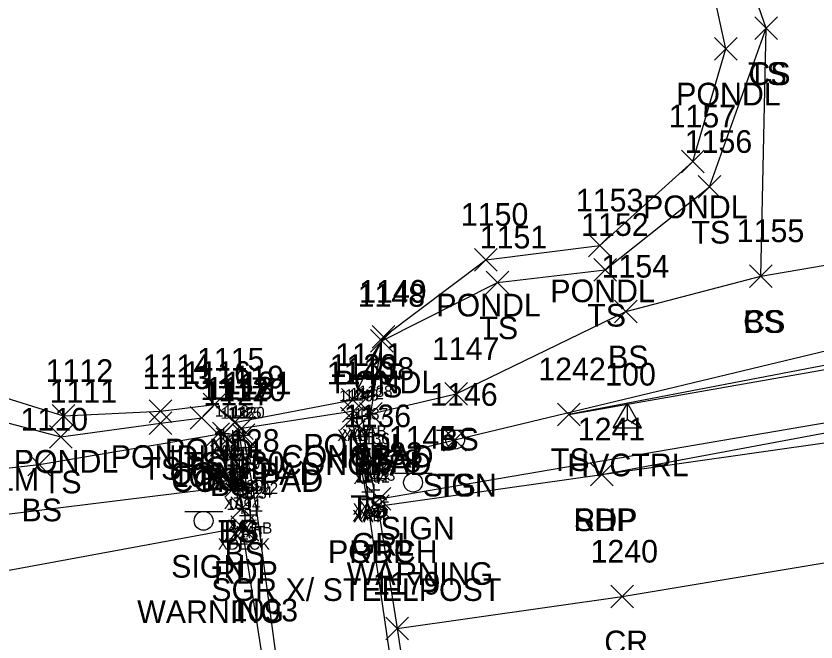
# Model space of a CAD drawing. Extents: x 1497084 to 1499861, y 734741 to 735567.
# Drawn here: x 1498306.3 to 1498376.8, y 735306.9 to 735362.1 of the extents above; entities that cross this region are included whole.
import ezdxf

# ---------------------------------------------------------------- set-up
doc = ezdxf.new("R2010")
doc.units = 0
for name, color, linetype in [('B_A', 7, 'Continuous'), ('B_I', 7, 'Continuous'), ('B_TIC', 7, 'Continuous'), ('BSUBM', 7, 'Continuous'), ('C_A', 7, 'Continuous'), ('C_I', 7, 'Continuous'), ('CPSM', 7, 'Continuous'), ('L_A', 7, 'Continuous'), ('L_C', 7, 'Continuous'), ('L_I', 7, 'Continuous'), ('L_TIC', 7, 'Continuous'), ('LAWE', 7, 'Continuous'), ('LELB', 7, 'Continuous'), ('LS', 7, 'Continuous'), ('P_A', 7, 'Continuous'), ('P_I', 7, 'Continuous'), ('P_TIC', 7, 'Continuous'), ('PET', 7, 'Continuous'), ('PRC', 7, 'Continuous'), ('PSP', 7, 'Continuous'), ('R_A', 7, 'Continuous'), ('R_C', 7, 'Continuous'), ('R_I', 7, 'Continuous'), ('R_TIC', 7, 'Continuous'), ('RGR', 7, 'Continuous'), ('S_A', 7, 'Continuous'), ('S_C', 7, 'Continuous'), ('S_I', 7, 'Continuous'), ('SSGN', 7, 'Continuous')]:
    doc.layers.add(name, color=color, linetype=linetype)

msp = doc.modelspace()

# ---------------------------------------------------------------- linework, layer by layer
at = {"layer": 'B_TIC'}
for p, q in [((1498337.564, 735327.025), (1498337.639, 735327.025)), ((1498335.891, 735326.633), (1498335.966, 735326.633)), ((1498336.333, 735326.701), (1498336.408, 735326.701)), ((1498336.333, 735326.701), (1498336.408, 735326.701)), ((1498336.796, 735326.829), (1498336.872, 735326.829)), ((1498324.607, 735325.287), (1498324.683, 735325.287)), ((1498325.413, 735325.098), (1498325.488, 735325.098)), ((1498326.022, 735325.12), (1498326.097, 735325.12)), ((1498326.343, 735325.152), (1498326.418, 735325.152)), ((1498337.167, 735325.038), (1498337.243, 735325.038)), ((1498337.167, 735325.038), (1498337.243, 735325.038)), ((1498337.347, 735322.858), (1498337.423, 735322.858)), ((1498325.918, 735320.65), (1498325.994, 735320.65)), ((1498337.26, 735320.143), (1498337.335, 735320.143)), ((1498337.872, 735320.321), (1498337.948, 735320.321)), ((1498337.204, 735319.55), (1498337.28, 735319.55)), ((1498337.31, 735319.467), (1498337.386, 735319.467)), ((1498337.31, 735319.467), (1498337.386, 735319.467)), ((1498337.817, 735319.634), (1498337.893, 735319.634)), ((1498326.218, 735318.714), (1498326.294, 735318.714)), ((1498326.218, 735318.714), (1498326.294, 735318.714)), ((1498326.481, 735318.057), (1498326.556, 735318.057)), ((1498326.481, 735318.057), (1498326.556, 735318.057)), ((1498326.967, 735318.137), (1498327.042, 735318.137)), ((1498327.485, 735318.469), (1498327.561, 735318.469)), ((1498326.238, 735317.05), (1498326.314, 735317.05))]:
    msp.add_line(p, q, dxfattribs=at)
for points in [[(1498335.887, 735326.133), (1498335.887, 735327.133)], [(1498336.329, 735326.201), (1498336.329, 735327.201)], [(1498336.329, 735326.201), (1498336.329, 735327.201)], [(1498336.793, 735326.329), (1498336.793, 735327.329)], [(1498337.06, 735327.025), (1498338.06, 735327.025)], [(1498337.56, 735326.525), (1498337.56, 735327.525)], [(1498335.387, 735326.633), (1498336.387, 735326.633)], [(1498335.829, 735326.701), (1498336.829, 735326.701)], [(1498335.829, 735326.701), (1498336.829, 735326.701)], [(1498336.293, 735326.829), (1498337.293, 735326.829)], [(1498324.604, 735324.787), (1498324.604, 735325.787)], [(1498325.409, 735324.598), (1498325.409, 735325.598)], [(1498326.018, 735324.62), (1498326.018, 735325.62)], [(1498326.339, 735324.652), (1498326.339, 735325.652)], [(1498324.104, 735325.287), (1498325.104, 735325.287)], [(1498324.909, 735325.098), (1498325.909, 735325.098)], [(1498325.518, 735325.12), (1498326.518, 735325.12)], [(1498325.839, 735325.152), (1498326.839, 735325.152)], [(1498336.664, 735325.038), (1498337.664, 735325.038)], [(1498336.664, 735325.038), (1498337.664, 735325.038)], [(1498337.164, 735324.538), (1498337.164, 735325.538)], [(1498337.164, 735324.538), (1498337.164, 735325.538)], [(1498336.844, 735322.858), (1498337.844, 735322.858)], [(1498337.344, 735322.358), (1498337.344, 735323.358)], [(1498325.415, 735320.65), (1498326.415, 735320.65)], [(1498325.915, 735320.15), (1498325.915, 735321.15)], [(1498337.256, 735319.643), (1498337.256, 735320.643)], [(1498337.869, 735319.821), (1498337.869, 735320.821)], [(1498336.756, 735320.143), (1498337.756, 735320.143)], [(1498337.201, 735319.05), (1498337.201, 735320.05)], [(1498337.307, 735318.967), (1498337.307, 735319.967)], [(1498337.307, 735318.967), (1498337.307, 735319.967)], [(1498337.369, 735320.321), (1498338.369, 735320.321)], [(1498337.814, 735319.134), (1498337.814, 735320.134)], [(1498336.701, 735319.55), (1498337.701, 735319.55)], [(1498336.807, 735319.467), (1498337.807, 735319.467)], [(1498336.807, 735319.467), (1498337.807, 735319.467)], [(1498337.314, 735319.634), (1498338.314, 735319.634)], [(1498325.715, 735318.714), (1498326.715, 735318.714)], [(1498325.715, 735318.714), (1498326.715, 735318.714)], [(1498326.215, 735318.214), (1498326.215, 735319.214)], [(1498326.215, 735318.214), (1498326.215, 735319.214)], [(1498326.477, 735317.557), (1498326.477, 735318.557)], [(1498326.477, 735317.557), (1498326.477, 735318.557)], [(1498326.963, 735317.637), (1498326.963, 735318.637)], [(1498327.482, 735317.969), (1498327.482, 735318.969)], [(1498325.977, 735318.057), (1498326.977, 735318.057)], [(1498325.977, 735318.057), (1498326.977, 735318.057)], [(1498326.463, 735318.137), (1498327.463, 735318.137)], [(1498326.982, 735318.469), (1498327.982, 735318.469)], [(1498326.235, 735316.55), (1498326.235, 735317.55)], [(1498325.735, 735317.05), (1498326.735, 735317.05)]]:
    msp.add_lwpolyline(points, dxfattribs=at)
at = {"layer": 'BSUBM'}
for points in [[(1498337.164, 735325.038), (1498337.56, 735327.025), (1498335.887, 735326.633), (1498337.201, 735319.55), (1498340.697, 735295.582)], [(1498337.307, 735319.467), (1498337.814, 735319.634), (1498337.869, 735320.321), (1498337.344, 735322.858), (1498337.164, 735325.038), (1498336.793, 735326.829), (1498336.329, 735326.701)], [(1498337.307, 735319.467), (1498337.256, 735320.143), (1498336.329, 735326.701)], [(1498324.604, 735325.287), (1498326.339, 735325.152), (1498327.482, 735318.469)], [(1498326.477, 735318.057), (1498326.963, 735318.137), (1498326.018, 735325.12), (1498325.409, 735325.098), (1498325.915, 735320.65), (1498326.215, 735318.714)], [(1498326.477, 735318.057), (1498326.215, 735318.714)], [(1498327.482, 735318.469), (1498330.708, 735294.208)]]:
    msp.add_lwpolyline(points, dxfattribs=at)
at = {"layer": 'CPSM'}
for p, q in [((1498358.924, 735325.805), (1498360.174, 735327.97)), ((1498361.424, 735325.805), (1498360.174, 735327.97)), ((1498360.174, 735326.527), (1498360.174, 735327.97)), ((1498358.924, 735325.805), (1498360.174, 735326.527)), ((1498360.174, 735326.527), (1498360.174, 735326.527)), ((1498360.174, 735326.527), (1498361.424, 735325.805)), ((1498358.924, 735325.805), (1498361.424, 735325.805))]:
    msp.add_line(p, q, dxfattribs=at)
at = {"layer": 'L_TIC'}
for points in [[(1498371.392, 735360.039), (1498373.392, 735362.039)], [(1498373.392, 735360.039), (1498371.392, 735362.039)], [(1498371.392, 735360.039), (1498373.392, 735362.039)], [(1498373.392, 735360.039), (1498371.392, 735362.039)], [(1498367.843, 735358.236), (1498369.843, 735360.236)], [(1498369.843, 735358.236), (1498367.843, 735360.236)], [(1498364.927, 735348.292), (1498366.927, 735350.292)], [(1498366.927, 735348.292), (1498364.927, 735350.292)], [(1498366.401, 735346.051), (1498368.401, 735348.051)], [(1498368.401, 735346.051), (1498366.401, 735348.051)], [(1498356.753, 735340.882), (1498358.753, 735342.882)], [(1498358.753, 735340.882), (1498356.753, 735342.882)], [(1498346.706, 735339.625), (1498348.706, 735341.625)], [(1498348.706, 735339.625), (1498346.706, 735341.625)], [(1498357.223, 735338.727), (1498359.223, 735340.727)], [(1498359.223, 735338.727), (1498357.223, 735340.727)], [(1498370.933, 735338.178), (1498372.933, 735340.178)], [(1498372.933, 735338.178), (1498370.933, 735340.178)], [(1498370.933, 735338.178), (1498372.933, 735340.178)], [(1498372.933, 735338.178), (1498370.933, 735340.178)], [(1498347.715, 735337.62), (1498349.715, 735339.62)], [(1498349.715, 735337.62), (1498347.715, 735339.62)], [(1498359.02, 735335.053), (1498361.02, 735337.053)], [(1498361.02, 735335.053), (1498359.02, 735337.053)], [(1498337.668, 735332.839), (1498339.668, 735334.839)], [(1498339.668, 735332.839), (1498337.668, 735334.839)], [(1498337.521, 735332.482), (1498339.521, 735334.482)], [(1498339.521, 735332.482), (1498337.521, 735334.482)], [(1498334.984, 735327.258), (1498336.984, 735329.258)], [(1498336.984, 735327.258), (1498334.984, 735329.258)], [(1498344.071, 735327.797), (1498346.071, 735329.797)], [(1498346.071, 735327.797), (1498344.071, 735329.797)], [(1498322.797, 735326.852), (1498324.797, 735328.852)], [(1498324.797, 735326.852), (1498322.797, 735328.852)], [(1498309.467, 735325.847), (1498311.467, 735327.847)], [(1498311.467, 735325.847), (1498309.467, 735327.847)], [(1498318.022, 735326.269), (1498320.022, 735328.269)], [(1498320.022, 735326.269), (1498318.022, 735328.269)], [(1498335.07, 735326.298), (1498337.07, 735328.298)], [(1498337.07, 735326.298), (1498335.07, 735328.298)], [(1498336.56, 735326.025), (1498338.56, 735328.025)], [(1498338.56, 735326.025), (1498336.56, 735328.025)], [(1498336.56, 735326.025), (1498338.56, 735328.025)], [(1498338.56, 735326.025), (1498336.56, 735328.025)], [(1498354.01, 735325.99), (1498356.01, 735327.99)], [(1498356.01, 735325.99), (1498354.01, 735327.99)], [(1498318.026, 735325.223), (1498320.026, 735327.223)], [(1498320.026, 735325.223), (1498318.026, 735327.223)], [(1498321.655, 735325.674), (1498323.655, 735327.674)], [(1498323.655, 735325.674), (1498321.655, 735327.674)], [(1498324.537, 735325.278), (1498326.537, 735327.278)], [(1498326.537, 735325.278), (1498324.537, 735327.278)], [(1498334.887, 735325.633), (1498336.887, 735327.633)], [(1498336.887, 735325.633), (1498334.887, 735327.633)], [(1498323.604, 735324.287), (1498325.604, 735326.287)], [(1498325.604, 735324.287), (1498323.604, 735326.287)], [(1498325.18, 735324.763), (1498327.18, 735326.763)], [(1498327.18, 735324.763), (1498325.18, 735326.763)], [(1498309.248, 735324.019), (1498311.248, 735326.019)], [(1498311.248, 735324.019), (1498309.248, 735326.019)], [(1498323.107, 735324.253), (1498325.107, 735326.253)], [(1498325.107, 735324.253), (1498323.107, 735326.253)], [(1498323.107, 735324.253), (1498325.107, 735326.253)], [(1498325.107, 735324.253), (1498323.107, 735326.253)], [(1498323.937, 735323.789), (1498325.937, 735325.789)], [(1498325.937, 735323.789), (1498323.937, 735325.789)], [(1498325.339, 735324.152), (1498327.339, 735326.152)], [(1498327.339, 735324.152), (1498325.339, 735326.152)], [(1498343.97, 735323.745), (1498345.97, 735325.745)], [(1498345.97, 735323.745), (1498343.97, 735325.745)], [(1498307.338, 735321.558), (1498309.338, 735323.558)], [(1498309.338, 735321.558), (1498307.338, 735323.558)], [(1498336.344, 735321.858), (1498338.344, 735323.858)], [(1498338.344, 735321.858), (1498336.344, 735323.858)], [(1498324.696, 735319.686), (1498326.696, 735321.686)], [(1498326.696, 735319.686), (1498324.696, 735321.686)], [(1498324.696, 735319.686), (1498326.696, 735321.686)], [(1498326.696, 735319.686), (1498324.696, 735321.686)], [(1498325.215, 735317.714), (1498327.215, 735319.714)], [(1498327.215, 735317.714), (1498325.215, 735319.714)], [(1498337.165, 735317.882), (1498339.165, 735319.882)], [(1498339.165, 735317.882), (1498337.165, 735319.882)]]:
    msp.add_lwpolyline(points, dxfattribs=at)
at = {"layer": 'LAWE'}
msp.add_lwpolyline([(1498275.465, 735378.169), (1498275.691, 735363.912), (1498285.128, 735344.959), (1498291.055, 735337.008), (1498299.895, 735330.144), (1498310.467, 735326.847), (1498319.022, 735327.269), (1498323.797, 735327.852), (1498325.537, 735326.278), (1498335.984, 735328.258), (1498338.668, 735333.839), (1498347.706, 735340.625), (1498357.753, 735341.882), (1498365.927, 735349.292), (1498368.843, 735359.236), (1498365.545, 735374.352), (1498361.929, 735386.408), (1498357.1, 735395.058), (1498355.999, 735402.309)], dxfattribs=at)
at = {"layer": 'LELB'}
for points in [[(1498337.56, 735327.025), (1498345.071, 735328.797), (1498360.02, 735336.053), (1498371.933, 735339.178), (1498383.259, 735341.124), (1498406.509, 735345.506), (1498447.671, 735353.973), (1498496.97, 735359.088), (1498555.389, 735373.271), (1498586.789, 735381.804), (1498595.746, 735372.636), (1498613.846, 735375.408), (1498671.762, 735381.92), (1498728.965, 735390.652), (1498788.671, 735399.739), (1498809.304, 735404.433), (1498807.972, 735434.197)], [(1498337.344, 735322.858), (1498344.97, 735324.745), (1498384.577, 735334.278), (1498409.205, 735337.398), (1498355.01, 735326.99), (1498382.446, 735331.791), (1498397.406, 735335.385), (1498428.619, 735342.289), (1498447.367, 735348.534), (1498497.982, 735350.736), (1498557.566, 735362.025), (1498577.341, 735369.5), (1498587.414, 735365.448), (1498611.954, 735369.89), (1498672.203, 735377.517), (1498729.566, 735386.751), (1498788.987, 735396.464), (1498814.154, 735401.685), (1498836.019, 735409.818), (1498851.622, 735410.693)], [(1498337.56, 735327.025), (1498338.521, 735333.482), (1498348.715, 735338.62), (1498358.223, 735339.727), (1498367.401, 735347.051), (1498372.392, 735361.039), (1498367.06, 735376.427), (1498362.838, 735387.164), (1498358.851, 735394.294), (1498358.462, 735401.834)], [(1498273.206, 735377.95), (1498273.394, 735363.671), (1498281.534, 735341.507), (1498289.608, 735335.025), (1498298.363, 735328.12), (1498310.248, 735325.019), (1498319.026, 735326.223), (1498322.655, 735326.674), (1498324.107, 735325.253)], [(1498371.933, 735339.178), (1498372.392, 735361.039)], [(1498163.46, 735296.334), (1498208.819, 735305.749), (1498256.363, 735322.464), (1498294.279, 735320.969), (1498308.338, 735322.558), (1498324.107, 735325.253), (1498324.604, 735325.287), (1498324.937, 735324.789), (1498325.696, 735320.686), (1498326.215, 735318.714)], [(1498163.032, 735290.457), (1498208.614, 735300.716), (1498247.233, 735311.969), (1498261.388, 735318.138), (1498270.355, 735314.142), (1498294.754, 735316.861), (1498325.696, 735320.686)]]:
    msp.add_lwpolyline(points, dxfattribs=at)
at = {"layer": 'LS'}
msp.add_lwpolyline([(1498326.339, 735325.152), (1498326.18, 735325.763), (1498336.07, 735327.298), (1498335.887, 735326.633)], dxfattribs=at)
at = {"layer": 'P_TIC'}
for points in [[(1498356.922, 735320.689), (1498358.922, 735322.689)], [(1498358.922, 735320.689), (1498356.922, 735322.689)], [(1498356.922, 735320.689), (1498358.922, 735322.689)], [(1498358.922, 735320.689), (1498356.922, 735322.689)], [(1498337.165, 735317.882), (1498339.165, 735319.882)], [(1498339.165, 735317.882), (1498337.165, 735319.882)], [(1498337.165, 735317.882), (1498339.165, 735319.882)], [(1498339.165, 735317.882), (1498337.165, 735319.882)], [(1498325.235, 735316.05), (1498327.235, 735318.05)], [(1498327.235, 735316.05), (1498325.235, 735318.05)], [(1498325.235, 735316.05), (1498327.235, 735318.05)], [(1498327.235, 735316.05), (1498325.235, 735318.05)], [(1498358.701, 735309.919), (1498360.701, 735311.919)], [(1498360.701, 735309.919), (1498358.701, 735311.919)], [(1498338.87, 735307.098), (1498340.87, 735309.098)], [(1498340.87, 735307.098), (1498338.87, 735309.098)], [(1498338.87, 735307.098), (1498340.87, 735309.098)], [(1498340.87, 735307.098), (1498338.87, 735309.098)]]:
    msp.add_lwpolyline(points, dxfattribs=at)
at = {"layer": 'PET'}
for points in [[(1498338.165, 735318.882), (1498357.922, 735321.689), (1498398.802, 735327.496), (1498451.3, 735335.225), (1498500.844, 735343.241), (1498558.124, 735351.585), (1498613.705, 735360.595), (1498673.075, 735369.219), (1498732.204, 735378.982), (1498789.956, 735387.815), (1498838.316, 735395.911), (1498888.985, 735404.303)], [(1498338.165, 735318.882), (1498339.87, 735308.098), (1498341.541, 735297.196), (1498360.209, 735300.184), (1498403.131, 735306.703), (1498454.967, 735313.532), (1498504.375, 735320.924), (1498560.617, 735329.108), (1498618.152, 735338.15), (1498676.466, 735346.785), (1498736.788, 735356.316), (1498793.849, 735365.136), (1498842.44, 735373.21), (1498892.667, 735381.868)], [(1498164.032, 735284.68), (1498207.879, 735294.082), (1498261.823, 735305.153), (1498326.235, 735317.05)], [(1498170.524, 735263.099), (1498210.239, 735272.243), (1498264.155, 735283.497), (1498329.951, 735295.031), (1498327.972, 735305.727), (1498326.235, 735317.05)]]:
    msp.add_lwpolyline(points, dxfattribs=at)
at = {"layer": 'PRC'}
msp.add_lwpolyline([(1498339.87, 735308.098), (1498359.701, 735310.919), (1498400.743, 735317.79), (1498454.013, 735324.129), (1498502.48, 735331.982), (1498559.278, 735340.308), (1498615.274, 735349.361), (1498674.884, 735357.799), (1498734.125, 735367.052), (1498791.712, 735376.051), (1498839.889, 735384.369), (1498890.74, 735392.787)], dxfattribs=at)
at = {"layer": 'PSP'}
msp.add_lwpolyline([(1498357.922, 735321.689), (1498398.081, 735329.187), (1498452.341, 735339.165), (1498499.614, 735346.687), (1498557.866, 735356.087), (1498612.391, 735365.432), (1498672.544, 735374.021), (1498730.824, 735383.147), (1498789.681, 735392.14), (1498809.844, 735395.769), (1498833.802, 735399.851), (1498855.601, 735403.687)], dxfattribs=at)
at = {"layer": 'R_TIC'}
for points in [[(1498337.329, 735318.531), (1498339.329, 735320.531)], [(1498339.329, 735318.531), (1498337.329, 735320.531)]]:
    msp.add_lwpolyline(points, dxfattribs=at)
at = {"layer": 'RGR'}
msp.add_lwpolyline([(1498338.329, 735319.531), (1498397.818, 735329.72), (1498437.964, 735337.775), (1498448.189, 735342.894)], dxfattribs=at)
at = {"layer": 'SSGN'}
for p, q in [((1498343.343, 735325.599), (1498346.676, 735325.599)), ((1498344.99, 735324.765), (1498344.99, 735324.765)), ((1498339.636, 735321.806), (1498342.969, 735321.806)), ((1498341.283, 735320.973), (1498341.283, 735320.973)), ((1498321.178, 735318.436), (1498324.511, 735318.436)), ((1498322.825, 735317.603), (1498322.825, 735317.603))]:
    msp.add_line(p, q, dxfattribs=at)
for centre in [(1498344.99, 735324.765), (1498341.283, 735320.973), (1498322.825, 735317.603)]:
    msp.add_circle(centre, 0.833, dxfattribs=at)

# ---------------------------------------------------------------- texts
at = {"layer": 'B_A'}
for s, p in [('XAB', (1498334.608, 735324.633)), ('XAT', (1498335.034, 735324.701)), ('XAT', (1498335.034, 735324.701)), ('XAT', (1498335.497, 735324.829)), ('XAB', (1498336.281, 735325.025)), ('XAB', (1498323.324, 735323.287)), ('XAT', (1498324.114, 735323.098)), ('XAT', (1498324.723, 735323.12)), ('XAB', (1498325.06, 735323.152)), ('XAT', (1498335.868, 735323.038)), ('XAB', (1498335.884, 735323.038)), ('XAT', (1498336.049, 735320.858)), ('XAT', (1498324.62, 735318.65)), ('XAT', (1498336.573, 735318.321)), ('XAB', (1498335.921, 735317.55)), ('XAT', (1498335.961, 735318.143)), ('XAT', (1498336.518, 735317.634)), ('XAT', (1498336.011, 735317.467)), ('XAT', (1498336.011, 735317.467)), ('XAT', (1498324.919, 735316.714)), ('XAT', (1498324.919, 735316.714)), ('XAT', (1498325.668, 735316.137)), ('XAB', (1498326.202, 735316.469)), ('XAT', (1498325.182, 735316.057)), ('XAT', (1498325.182, 735316.057)), ('XDECK', (1498324.077, 735315.05))]:
    msp.add_text(s, height=1, dxfattribs=at).set_placement(p)
at = {"layer": 'B_I'}
for s, p in [('1140', (1498334.781, 735328.133)), ('1143', (1498335.266, 735328.201)), ('1143', (1498335.266, 735328.201)), ('1142', (1498335.73, 735328.329)), ('1138', (1498336.497, 735328.525)), ('1118', (1498323.824, 735326.787)), ('1126', (1498324.319, 735326.598)), ('1125', (1498324.955, 735326.62)), ('1120', (1498325.233, 735326.652)), ('1137', (1498336.101, 735326.538)), ('1137', (1498336.101, 735326.538)), ('1136', (1498336.253, 735324.358)), ('1129', (1498324.848, 735322.15)), ('1134', (1498336.806, 735321.821)), ('1144', (1498336.138, 735321.05)), ('1135', (1498336.193, 735321.643)), ('1133', (1498336.751, 735321.134)), ('1132', (1498336.244, 735320.967)), ('1132', (1498336.244, 735320.967)), ('1130', (1498325.108, 735320.214)), ('1130', (1498325.108, 735320.214)), ('1124', (1498325.9, 735319.637)), ('1122', (1498326.419, 735319.969)), ('1123', (1498325.414, 735319.557)), ('1123', (1498325.414, 735319.557)), ('1094', (1498324.849, 735318.55))]:
    msp.add_text(s, height=1, dxfattribs=at).set_placement(p)
at = {"layer": 'C_A'}
msp.add_text('HVCTRL', height=2, dxfattribs=at).set_placement((1498354.867, 735321.527))
at = {"layer": 'C_I'}
msp.add_text('100', height=2, dxfattribs=at).set_placement((1498358.213, 735329.527))
at = {"layer": 'L_A'}
for s, p in [('TS', (1498370.802, 735356.039)), ('CS', (1498370.833, 735356.039)), ('PONDL', (1498364.465, 735354.236)), ('PONDL', (1498361.549, 735344.292)), ('TS', (1498365.81, 735342.051)), ('PONDL', (1498353.375, 735336.882)), ('PONDL', (1498343.328, 735335.625)), ('TS', (1498356.632, 735334.727)), ('CS', (1498370.374, 735334.178)), ('BS', (1498370.374, 735334.178)), ('TS', (1498347.125, 735333.62)), ('BS', (1498358.46, 735331.053)), ('PONDL', (1498334.29, 735328.839)), ('TS', (1498336.931, 735328.482)), ('BS', (1498343.512, 735323.797)), ('PONDL', (1498319.419, 735322.852)), ('PONDL', (1498331.606, 735323.258)), ('PONDL', (1498314.644, 735322.269)), ('CONCPAD', (1498329.715, 735322.298)), ('PONDL', (1498306.089, 735321.847)), ('TS', (1498321.064, 735321.674)), ('CONCPAD', (1498329.533, 735321.633)), ('TS', (1498335.969, 735322.025)), ('BS', (1498336.001, 735322.025)), ('TS', (1498353.419, 735321.99)), ('TS', (1498317.435, 735321.223)), ('CONCPAD', (1498319.826, 735320.763)), ('PONDL', (1498321.159, 735321.278)), ('TS', (1498308.657, 735320.019)), ('CONCPAD', (1498319.985, 735320.152)), ('TS', (1498322.516, 735320.253)), ('BS', (1498322.548, 735320.253)), ('BS', (1498323.045, 735320.287)), ('BS', (1498323.378, 735319.789)), ('TS', (1498343.38, 735319.745)), ('BS', (1498306.779, 735317.558)), ('TS', (1498335.753, 735317.858)), ('TS', (1498324.106, 735315.686)), ('BS', (1498324.137, 735315.686)), ('BS', (1498324.656, 735313.714)), ('PORCH', (1498333.787, 735313.882))]:
    msp.add_text(s, height=2, dxfattribs=at).set_placement(p)
at = {"layer": 'L_C'}
msp.add_text('4 S. DEAD ELM', height=2, dxfattribs=at).set_placement((1498289.149, 735320.253))
at = {"layer": 'L_I'}
for s, p in [('1157', (1498363.801, 735352.292)), ('1156', (1498365.22, 735350.051)), ('1153', (1498355.627, 735344.882)), ('1150', (1498345.494, 735343.625)), ('1152', (1498356.097, 735342.727)), ('1155', (1498369.807, 735342.178)), ('1155', (1498369.807, 735342.178)), ('1151', (1498347.156, 735341.62)), ('1154', (1498357.894, 735339.053)), ('1148', (1498336.395, 735336.482)), ('1149', (1498336.534, 735336.839)), ('1147', (1498342.945, 735331.797)), ('1115', (1498322.238, 735330.852)), ('1141', (1498334.425, 735331.258)), ('1114', (1498317.463, 735330.269)), ('1139', (1498333.936, 735330.298)), ('1138', (1498335.434, 735330.025)), ('1138', (1498335.434, 735330.025)), ('1242', (1498352.317, 735329.99)), ('1112', (1498308.908, 735329.847)), ('1113', (1498317.467, 735329.223)), ('1116', (1498321.041, 735329.674)), ('1119', (1498323.97, 735329.278)), ('1140', (1498333.675, 735329.633)), ('1121', (1498324.621, 735328.763)), ('1111', (1498309.256, 735328.019)), ('1117', (1498322.548, 735328.253)), ('1117', (1498322.548, 735328.253)), ('1127', (1498322.811, 735327.789)), ('1118', (1498323.045, 735328.287)), ('1120', (1498324.127, 735328.152)), ('1146', (1498342.789, 735327.745)), ('1136', (1498335.163, 735325.858)), ('1110', (1498306.693, 735325.558)), ('1128', (1498323.57, 735323.686)), ('1128', (1498323.57, 735323.686)), ('1130', (1498324.002, 735321.714)), ('1178', (1498336.039, 735321.882))]:
    msp.add_text(s, height=2, dxfattribs=at).set_placement(p)
at = {"layer": 'P_A'}
for s, p in [('SHP', (1498355.457, 735316.689)), ('RDP', (1498355.41, 735316.689)), ('RDP', (1498335.653, 735313.882)), ('RDP', (1498335.653, 735313.882)), ('RDP', (1498323.723, 735312.05)), ('RDP', (1498323.723, 735312.05)), ('CR', (1498358.134, 735305.919))]:
    msp.add_text(s, height=2, dxfattribs=at).set_placement(p)
at = {"layer": 'P_I'}
for s, p in [('1241', (1498355.796, 735324.689)), ('1241', (1498355.796, 735324.689)), ('1178', (1498336.039, 735321.882)), ('1178', (1498336.039, 735321.882)), ('1094', (1498323.463, 735320.05)), ('1094', (1498323.463, 735320.05)), ('1240', (1498356.921, 735313.919)), ('1179', (1498337.736, 735311.098)), ('1179', (1498337.736, 735311.098)), ('1093', (1498325.2, 735308.727)), ('1093', (1498325.2, 735308.727))]:
    msp.add_text(s, height=2, dxfattribs=at).set_placement(p)
at = {"layer": 'R_A'}
msp.add_text('GRL', height=2, dxfattribs=at).set_placement((1498335.873, 735314.531))
at = {"layer": 'R_C'}
msp.add_text('SGR X/ STEELPOST', height=2, dxfattribs=at).set_placement((1498323.503, 735310.531))
at = {"layer": 'R_I'}
msp.add_text('1183', height=2, dxfattribs=at).set_placement((1498336.203, 735322.531))
at = {"layer": 'S_A'}
for p in [(1498342.128, 735319.745), (1498338.421, 735315.953), (1498319.963, 735312.583)]:
    msp.add_text('SIGN', height=2, dxfattribs=at).set_placement(p)
at = {"layer": 'S_C'}
for p in [(1498335.429, 735311.953), (1498316.971, 735308.583)]:
    msp.add_text('WARNING', height=2, dxfattribs=at).set_placement(p)
at = {"layer": 'S_I'}
for s, p in [('1146', (1498342.789, 735327.745)), ('1145', (1498339.137, 735323.953)), ('1095', (1498320.034, 735320.583))]:
    msp.add_text(s, height=2, dxfattribs=at).set_placement(p)

doc.saveas('drawing.dxf')
